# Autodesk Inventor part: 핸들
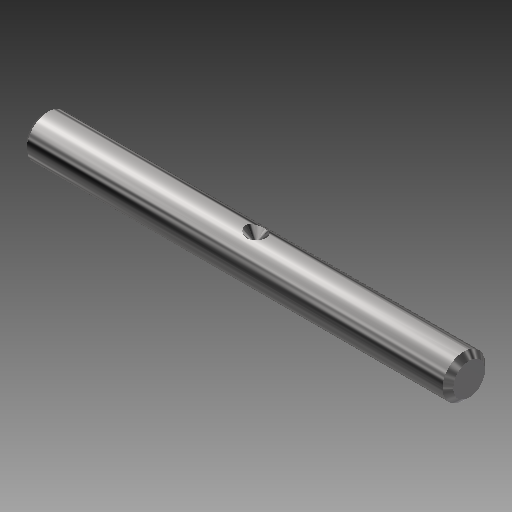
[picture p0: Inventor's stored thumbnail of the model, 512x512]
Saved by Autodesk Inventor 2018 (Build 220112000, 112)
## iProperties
Created: 2019-04
Part Number: 핸들
Material: 스테인리스강
Document SubType Name: Modeling
Designer: mduedu
Density: 1 g/cm^3
Appearance: 반광택
Author: mduedu
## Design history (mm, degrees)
sketch "스케치1"
  geometry: C1 r 4 at (0, 0); 1 further point
  constraints: 1 centre point, 1 coincident
  dimensions: "d0" = 8 diameter of C1
extrude "돌출1" new body sketch "스케치1" stored distance "d1" = 80; taper "d2" = 0 deg
chamfer "모따기1" distance "d3" = 1; stored, may be unused: second distance "d4" = 2, angle "d5" = 45 deg
sketch "스케치2"
  geometry: L1 (-39, 4)-(39, 4) reference; L2 (0, 4)-(0, 2); L3 (0, 2)-(2, 4); L4 (0, 4)-(2, 4); 1 further point
  constraints: 6 end point, 2 perpendicular, 1 midpoint, 1 point on line
  dimensions: "d6" = 4 diameter of L3.end L2; "d8" = 45 deg angle of L3 L2
revolve "회전1" sketch "스케치2" stored, may be unused: angle "d10" = 90 deg
node "작업점1"
  node "작업축1"
  node "작업 평면1"
node "솔리드1"
